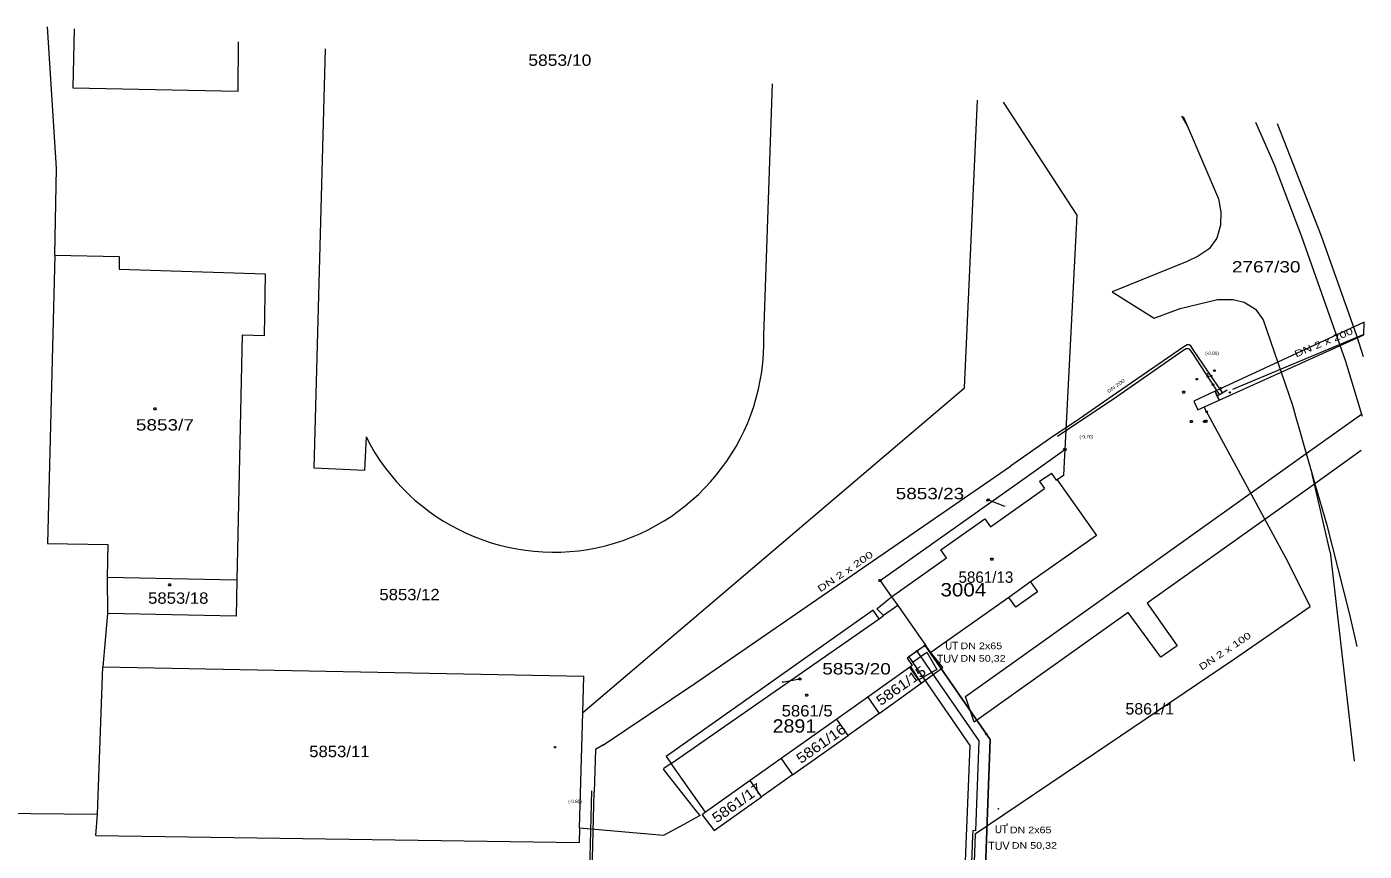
# Model space of a CAD drawing. Extents: x -725191 to -724881, y -978080 to -977718.
# Drawn here: x -725081.4 to -724880.9, y -977841.3 to -977717.7 of the extents above; entities that cross this region are included whole.
import ezdxf
from ezdxf.enums import TextEntityAlignment as Align

# ---------------------------------------------------------------- set-up
doc = ezdxf.new("R2010")
doc.units = 0
doc.header["$LTSCALE"] = 0.48
doc.header["$PDMODE"] = 32
doc.header["$PDSIZE"] = 0.24
for name, color, linetype, lineweight in [('1', 7, 'Continuous', 13), ('4', 7, 'Continuous', 13), ('46', 7, 'Continuous', 13), ('48', 7, 'Continuous', 13), ('5', 7, 'Continuous', 13), ('58', 7, 'Continuous', 13), ('63', 7, 'Continuous', 13), ('7', 7, 'Continuous', 13), ('8', 7, 'Continuous', 13)]:
    doc.layers.add(name, color=color, linetype=linetype, lineweight=lineweight)
doc.layers.add('2', color=7, linetype='Continuous')
doc.layers.add('20', color=7, linetype='Continuous')

msp = doc.modelspace()

# ---------------------------------------------------------------- linework, layer by layer
at = {"layer": '1'}
for p, q in [((-725077, -977738.94), (-725078.351, -977717.731)), ((-725074.329, -977718.048), (-725074.53, -977726.89)), ((-725038.37, -977783.91), (-725036.662, -977721.018)), ((-724970.94, -977764), (-724969.634, -977726.305)), ((-724940.83, -977771.89), (-724938.905, -977728.728)), ((-724935.028, -977729.034), (-724924, -977746)), ((-724907.45, -977732.56), (-724902.77, -977743.52)), ((-724887.3, -977749.13), (-724893.921, -977732.276)), ((-725077.23, -977751.96), (-725077, -977738.94)), ((-724924, -977746), (-724925.8, -977781.13)), ((-724882.02, -977764.07), (-724887.3, -977749.13)), ((-724881.025, -977767.222), (-724882.02, -977764.07)), ((-724998.05, -977820.52), (-724940.83, -977771.89)), ((-724889.6, -977781.71), (-724888.72, -977784.8)), ((-724927.04, -977785.71), (-724926.96, -977785.65)), ((-724936.94, -977792.71), (-724928.83, -977786.98)), ((-724886, -977796.5), (-724882.434, -977827.833)), ((-725070.03, -977813.69), (-724997.92, -977815.1)), ((-724998.05, -977820.52), (-724997.92, -977815.1)), ((-724955.36, -977818.24), (-724953.63, -977820.69)), ((-724998.55, -977837.86), (-724998.05, -977820.52)), ((-724966.61, -977829.88), (-724958.28, -977823.99)), ((-724985.58, -977827.13), (-724984.83, -977828.19)), ((-724978.36, -977838.24), (-724971.26, -977833.17)), ((-725071.09, -977838.97), (-725070.85, -977835.77)), ((-725071.09, -977838.97), (-724998.61, -977840.03))]:
    msp.add_line(p, q, dxfattribs=at)
for points in [[(-725074.53, -977726.89), (-725049.77, -977727.38), (-725049.675, -977719.992)], [(-724908.046, -977731.162), (-724907.45, -977732.56), (-724908.241, -977731.146)], [(-724902.77, -977743.52), (-724902.41, -977745.49), (-724902.45, -977747.49), (-724903.01, -977749.42), (-724904.15, -977751.03), (-724905.81, -977752.14), (-724907.48, -977752.94), (-724918.72, -977757.47), (-724912.38, -977761.4), (-724908.5, -977759.96), (-724902.92, -977758.61), (-724900.55, -977758.6), (-724898.9, -977759.02), (-724897.23, -977760.09), (-724896.04, -977761.68), (-724891.68, -977774.44)], [(-725077.23, -977751.96), (-725078.33, -977795.22), (-725069.29, -977795.35), (-725069.39, -977800.29)], [(-725077.23, -977751.96), (-725067.57, -977752.18), (-725067.61, -977754.09), (-725045.68, -977754.76), (-725045.86, -977764.05), (-725049.15, -977763.97), (-725049.94, -977800.71), (-725069.39, -977800.29)], [(-724891.68, -977774.44), (-724891.05, -977776.65), (-724890.76, -977777.65), (-724889.6, -977781.71)], [(-725030.58, -977779.22), (-725030.79, -977784.25), (-725038.37, -977783.91)], [(-724953.51, -977800.76), (-724931.26, -977785), (-724925.8, -977781.13)], [(-724925.8, -977781.13), (-724925.89, -977782.91), (-724925.95, -977784), (-724926, -977785)], [(-724926, -977785), (-724926.96, -977785.65), (-724921.07, -977793.98), (-724930.95, -977800.97), (-724929.91, -977802.44), (-724933.17, -977804.75), (-724934.21, -977803.28), (-724945.89, -977811.54), (-724946.67, -977810.44), (-724949.45, -977812.4), (-724948.67, -977813.51)], [(-724927.04, -977785.71), (-724927.75, -977784.71), (-724929.58, -977785.92), (-724928.83, -977786.98)], [(-724886, -977796.5), (-724888.37, -977786.29), (-724888.72, -977784.8), (-724888.31, -977786.24), (-724886.59, -977792.26)], [(-724943.52, -977797.36), (-724944.38, -977796.14), (-724937.8, -977791.49), (-724936.94, -977792.71)], [(-724886.59, -977792.26), (-724883.12, -977805.83), (-724882.035, -977810.662)], [(-724984.83, -977828.19), (-724953.63, -977806.49), (-724953, -977806), (-724954, -977805), (-724951.78, -977803.21), (-724943.52, -977797.36)], [(-725069.39, -977800.29), (-725069.35, -977805.69), (-725070.03, -977813.69)], [(-725049.94, -977800.71), (-725050.06, -977806.11), (-725069.35, -977805.69)], [(-724953.51, -977800.76), (-724952.97, -977801.52), (-724951.78, -977803.21)], [(-724951.78, -977803.21), (-724950.86, -977804.52), (-724946.67, -977810.44)], [(-724953.63, -977806.49), (-724954.56, -977805.18), (-724985.58, -977827.13)], [(-724953.63, -977820.69), (-724947.35, -977816.15), (-724944.08, -977813.8), (-724945.89, -977811.54)], [(-725085.88, -977835.64), (-725070.85, -977835.77), (-725070.03, -977813.69)], [(-724948.67, -977813.51), (-724948.87, -977813.65), (-724955.36, -977818.24)], [(-724953.63, -977820.69), (-724958.28, -977823.99), (-724960.01, -977821.54), (-724968.34, -977827.43), (-724966.61, -977829.88), (-724971.26, -977833.17), (-724973, -977830.72)], [(-724984.83, -977828.19), (-724985.93, -977828.95), (-724986, -977829)], [(-724973, -977830.72), (-724979.69, -977835.46), (-724984.83, -977828.19)], [(-724980.5, -977836), (-724981.03, -977835.33), (-724982.13, -977833.93), (-724985.83, -977829.22), (-724986, -977829)], [(-724980.5, -977836), (-724981.23, -977836.4), (-724982.37, -977837.02), (-724986, -977839)], [(-724979.69, -977835.46), (-724980.17, -977835.87), (-724978.36, -977838.24)], [(-724986, -977839), (-724998.55, -977837.86), (-724998.61, -977840.03)]]:
    msp.add_lwpolyline(points, dxfattribs=at)
msp.add_arc((-725002.4513, -977764.9825), 31.5266, 206.84653, 1.78587, dxfattribs=at)
at = {"layer": '4'}
for p, q in [((-724897.2, -977732.017), (-724894.4, -977738.4)), ((-724930.95, -977800.97), (-724934.21, -977803.28)), ((-724950.86, -977804.52), (-724953, -977806)), ((-724947.35, -977816.15), (-724948.87, -977813.65)), ((-724955.36, -977818.24), (-724960.01, -977821.54)), ((-724968.34, -977827.43), (-724973, -977830.72))]:
    msp.add_line(p, q, dxfattribs=at)
for points in [[(-724894.4, -977738.4), (-724890.3, -977749.17), (-724883.71, -977767.86)], [(-724883.71, -977767.86), (-724881.32, -977775.81), (-724881.232, -977776.106)], [(-724915.65, -977800.29), (-724889.6, -977781.71), (-724881.32, -977775.81), (-724881.223, -977775.74)], [(-724881.352, -977781.278), (-724888.31, -977786.24), (-724888.37, -977786.29), (-724913.46, -977804.17)], [(-724939.38, -977821.98), (-724940.71, -977818.13), (-724915.65, -977800.29)], [(-724913.46, -977804.17), (-724908.96, -977810.54), (-724911.4, -977812.26), (-724916.3, -977805.53), (-724939.38, -977821.98)]]:
    msp.add_lwpolyline(points, dxfattribs=at)
at = {"layer": '48'}
msp.add_lwpolyline([(-724904.36, -977769.719), (-724904.324, -977769.743), (-724904.328, -977769.786), (-724904.368, -977769.806), (-724904.405, -977769.782), (-724904.401, -977769.739)], close=True, dxfattribs=at)
for p in [(-724903.367, -977769.277), (-724906.017, -977770.566)]:
    msp.add_point(p, dxfattribs=at)
at = {"layer": '5'}
for points in [[(-725062.14, -977774.84), (-725062.05, -977774.99), (-725062.14, -977775.14), (-725062.32, -977775.14), (-725062.41, -977774.99), (-725062.32, -977774.84)], [(-724936.65, -977797.39), (-724936.56, -977797.54), (-724936.65, -977797.69), (-724936.83, -977797.69), (-724936.92, -977797.54), (-724936.83, -977797.39)], [(-725059.94, -977801.27), (-725059.85, -977801.42), (-725059.94, -977801.57), (-725060.12, -977801.57), (-725060.21, -977801.42), (-725060.12, -977801.27)], [(-724964.4, -977817.77), (-724964.31, -977817.92), (-724964.4, -977818.07), (-724964.58, -977818.07), (-724964.67, -977817.92), (-724964.58, -977817.77)]]:
    msp.add_lwpolyline(points, close=True, dxfattribs=at)
at = {"layer": '58'}
for points in [[(-724907.89, -977772.37), (-724907.8, -977772.52), (-724907.89, -977772.67), (-724908.07, -977772.67), (-724908.16, -977772.52), (-724908.07, -977772.37)], [(-724906.73, -977776.78), (-724906.64, -977776.93), (-724906.73, -977777.08), (-724906.91, -977777.08), (-724907, -977776.93), (-724906.91, -977776.78)], [(-724904.76, -977776.78), (-724904.67, -977776.93), (-724904.76, -977777.08), (-724904.94, -977777.08), (-724905.03, -977776.93), (-724904.94, -977776.78)], [(-724904.56, -977776.7), (-724904.47, -977776.85), (-724904.56, -977777), (-724904.74, -977777), (-724904.83, -977776.85), (-724904.74, -977776.7)]]:
    msp.add_lwpolyline(points, close=True, dxfattribs=at)
at = {"layer": '63'}
for p, q in [((-724880.905, -977762.044), (-724903.26, -977772.39)), ((-724902.66, -977773.73), (-724880.949, -977763.933)), ((-724880.947, -977763.868), (-724900.647, -977772.107)), ((-724901.44, -977772.23), (-724902.97, -977773.09)), ((-724927.61, -977779.16), (-724933.96, -977783.61)), ((-724939.222, -977838.756), (-724940.562, -977875.291))]:
    msp.add_line(p, q, dxfattribs=at)
for points in [[(-724880.905, -977762.032), (-724903.26, -977772.39), (-724902.66, -977773.73), (-724880.949, -977763.936)], [(-724880.905, -977762.032), (-724903.26, -977772.39), (-724902.66, -977773.73), (-724880.949, -977763.936)], [(-724904.47, -977770.179), (-724904.402, -977770.077), (-724904.28, -977770.089), (-724904.226, -977770.203), (-724904.294, -977770.305), (-724904.416, -977770.293)], [(-724903.735, -977770.091), (-724903.797, -977770.196), (-724903.919, -977770.192), (-724903.98, -977770.081), (-724903.919, -977769.976), (-724903.796, -977769.98)], [(-724903.718, -977771.376), (-724903.647, -977771.255), (-724903.507, -977771.26), (-724903.438, -977771.386), (-724903.508, -977771.507), (-724903.648, -977771.502)], [(-724902.3, -977771.94), (-724902.357, -977772.048), (-724902.479, -977772.05), (-724902.545, -977771.942), (-724902.489, -977771.833), (-724902.366, -977771.832)], [(-724902.97, -977773.09), (-724903.26, -977772.39), (-724906.45, -977773.87), (-724905.87, -977775.18), (-724902.66, -977773.73)], [(-724901.067, -977772.658), (-724901.139, -977772.609), (-724901.13, -977772.522), (-724901.049, -977772.484), (-724900.976, -977772.533), (-724900.985, -977772.62)], [(-724904.383, -977775.466), (-724904.455, -977775.586), (-724904.595, -977775.578), (-724904.663, -977775.451), (-724904.59, -977775.331), (-724904.45, -977775.339)], [(-724946.744, -977810.509), (-724949.211, -977812.215), (-724940.029, -977825.495), (-724942.001, -977873.733), (-724942.701, -977873.705), (-724942.819, -977876.703), (-724942.12, -977876.73), (-724943.226, -977905.12), (-724943.926, -977905.093), (-724944.039, -977908.091), (-724934.046, -977908.468), (-724936.266, -977967.326), (-724933.268, -977967.439), (-724931.048, -977908.581), (-724930.349, -977908.607), (-724930.236, -977905.61), (-724940.229, -977905.233), (-724938.908, -977876.858), (-724932.627, -977877.107), (-724932.509, -977874.109), (-724938.79, -977873.86), (-724936.993, -977824.611)], [(-724946.744, -977810.509), (-724949.211, -977812.215), (-724940.029, -977825.495), (-724942.001, -977873.733), (-724942.701, -977873.705), (-724942.819, -977876.703), (-724942.12, -977876.73), (-724943.226, -977905.12), (-724943.926, -977905.093), (-724944.039, -977908.091), (-724934.046, -977908.468), (-724936.266, -977967.326), (-724933.268, -977967.439), (-724931.048, -977908.581), (-724930.349, -977908.607), (-724930.236, -977905.61), (-724940.229, -977905.233), (-724938.908, -977876.858), (-724932.627, -977877.107), (-724932.509, -977874.109), (-724938.79, -977873.86), (-724936.993, -977824.611)], [(-724946.744, -977810.509), (-724949.211, -977812.215), (-724940.029, -977825.495), (-724942.001, -977873.733), (-724942.701, -977873.705), (-724942.819, -977876.703), (-724942.12, -977876.73), (-724943.226, -977905.12), (-724943.926, -977905.093), (-724944.039, -977908.091), (-724934.046, -977908.468), (-724936.266, -977967.326), (-724933.268, -977967.439), (-724931.048, -977908.581), (-724930.349, -977908.607), (-724930.236, -977905.61), (-724940.229, -977905.233), (-724938.908, -977876.858), (-724932.627, -977877.107), (-724932.509, -977874.109), (-724938.79, -977873.86), (-724936.993, -977824.611)], [(-724935.751, -977834.958), (-724935.72, -977834.972), (-724935.717, -977835.007), (-724935.747, -977835.028), (-724935.779, -977835.013), (-724935.781, -977834.979)], [(-724934.443, -977837.322), (-724934.475, -977837.306), (-724934.475, -977837.271), (-724934.445, -977837.252), (-724934.414, -977837.268), (-724934.413, -977837.303)]]:
    msp.add_lwpolyline(points, close=True, dxfattribs=at)
for points in [[(-724902.108, -977772.676), (-724906.6, -977766.06), (-724906.9, -977765.55), (-724907.14, -977765.44), (-724907.44, -977765.44), (-724907.95, -977765.74), (-724918.03, -977772.65), (-724924.24, -977776.96), (-724927.61, -977779.16)], [(-724902.598, -977772.886), (-724906.73, -977766.55), (-724907.05, -977766.1), (-724907.27, -977766.03), (-724907.6, -977766.02), (-724908.11, -977766.33), (-724918, -977773.2), (-724926.92, -977779.14)], [(-724939.222, -977838.756), (-724921.29, -977826.63), (-724900.35, -977812.47), (-724889.03, -977804.64), (-724892.31, -977797.99), (-724904.918, -977774.75)], [(-724995.11, -977825.47), (-724981.28, -977816.18), (-724933.96, -977783.61)], [(-724946.744, -977810.509), (-724949.211, -977812.215), (-724940.029, -977825.495), (-724942.001, -977873.733), (-724942.701, -977873.705), (-724942.819, -977876.703), (-724942.12, -977876.73), (-724943.226, -977905.12), (-724943.926, -977905.093), (-724944.039, -977908.091), (-724943.34, -977908.117), (-724934.046, -977908.468), (-724936.266, -977967.326), (-724933.268, -977967.439), (-724931.048, -977908.581), (-724930.349, -977908.607), (-724930.236, -977905.61), (-724930.935, -977905.583), (-724933.933, -977905.47)], [(-724948.678, -977813.053), (-724946.5, -977811.51), (-724944.98, -977814.1), (-724947.67, -977815.66), (-724949.073, -977813.691)], [(-724947.978, -977811.362), (-724938.71, -977824.766), (-724939.204, -977838.257), (-724939.604, -977838.242), (-724939.636, -977839.037)], [(-724946.744, -977810.509), (-724936.993, -977824.611), (-724938.79, -977873.86)], [(-724995.056, -977825.449), (-724996.156, -977826.109), (-724996.376, -977832.498)], [(-724996.78, -977832.3), (-724997.07, -977844.29), (-724997.12, -977846.74), (-724997.13, -977847.34), (-724997.28, -977847.6), (-724997.53, -977847.71), (-724998.14, -977847.69), (-725010.12, -977847.35), (-725022.19, -977846.94), (-725034.17, -977846.58), (-725046.16, -977846.17), (-725052.297, -977846.041), (-725054.5, -977845.99), (-725056.407, -977845.955), (-725066.64, -977845.74), (-725078.71, -977845.31), (-725090.71, -977845.05), (-725102.48, -977844.75), (-725114.72, -977844.37)], [(-725114.7, -977844.66), (-725102.42, -977845.11), (-725090.73, -977845.48), (-725078.78, -977845.7), (-725066.72, -977846.15), (-725056.681, -977846.35), (-725054.7, -977846.39), (-725052.296, -977846.437), (-725045.64, -977846.57), (-725033.74, -977847.05), (-725021.75, -977847.47), (-725009.76, -977847.84), (-724997.78, -977848.14), (-724997.15, -977848.14), (-724996.88, -977847.98), (-724996.72, -977847.77), (-724996.68, -977847.12), (-724996.65, -977844.4), (-724996.35, -977832.44)], [(-724939.636, -977839.037), (-724940.981, -977875.775), (-724940.582, -977875.791), (-724940.821, -977881.133), (-724941.626, -977902.478), (-724941.784, -977906.675), (-724932.491, -977907.026), (-724934.684, -977965.184)]]:
    msp.add_lwpolyline(points, dxfattribs=at)
for p in [(-724947.978, -977811.362), (-724946.744, -977810.509), (-724937.562, -977823.788), (-725002.25, -977825.739)]:
    msp.add_point(p, dxfattribs=at)
at = {"layer": '7'}
for p, q in [((-724934.78, -977789.64), (-724937.32, -977788.67)), ((-724968.18, -977815.97), (-724965.53, -977815.5))]:
    msp.add_line(p, q, dxfattribs=at)
for points in [[(-724937.428, -977788.532), (-724937.255, -977788.502), (-724937.148, -977788.64), (-724937.212, -977788.808), (-724937.385, -977788.838), (-724937.492, -977788.7)], [(-724965.367, -977815.562), (-724965.499, -977815.677), (-724965.662, -977815.615), (-724965.693, -977815.438), (-724965.561, -977815.323), (-724965.398, -977815.385)]]:
    msp.add_lwpolyline(points, close=True, dxfattribs=at)
at = {"layer": '8'}
for points in [[(-724925.71, -977780.98), (-724925.62, -977781.13), (-724925.71, -977781.28), (-724925.89, -977781.28), (-724925.98, -977781.13), (-724925.89, -977780.98)], [(-724953.42, -977800.61), (-724953.33, -977800.76), (-724953.42, -977800.91), (-724953.6, -977800.91), (-724953.69, -977800.76), (-724953.6, -977800.61)]]:
    msp.add_lwpolyline(points, close=True, dxfattribs=at)

# ---------------------------------------------------------------- texts
at = {"layer": '2'}
for s, height, width, p in [('5853/10', 1.7, 1.15, (-725006.243, -977723.59)), ('2767/30', 1.7, 1.25, (-724900.743, -977754.57)), ('5853/7', 1.7, 1.25, (-725065.083, -977778.27)), ('5853/23', 0.1, 1.25, (-724934.766, -977789.64)), ('5853/12', 1.7, 1.1, (-725028.573, -977803.71)), ('5853/18', 1.7, 1.1, (-725063.253, -977804.24)), ('5861/5', 1.7, 1.1, (-724968.263, -977821.14)), ('5861/1', 1.7, 1.05, (-724916.713, -977820.84)), ('5853/11', 1.7, 1.1, (-725039.093, -977827.23))]:
    msp.add_text(s, height=height, dxfattribs=dict(at, width=width)).set_placement(p)
msp.add_text('5861/13', height=1.7, dxfattribs=at).set_placement((-724941.743, -977801.1))
at = {"layer": '2', "width": 1.15}
for s, p in [('5861/15', (-724953.405, -977819.597)), ('5861/16', (-724965.375, -977828.277)), ('5861/17', (-724978.015, -977837.177))]:
    msp.add_text(s, height=1.53, rotation=35.122, dxfattribs=at).set_placement(p)
at = {"layer": '2', "width": 1.25}
msp.add_text('5853/20', height=0.1, dxfattribs=at).set_placement((-724968.18, -977815.97), align=Align.CENTER)
at = {"layer": '20', "width": 1.1}
msp.add_text('2891', height=2, dxfattribs=at).set_placement((-724966.343, -977823.562), align=Align.CENTER)
at = {"layer": '46'}
for s, p in [('(-0,80)', (-724903.7215, -977766.934)), ('(-0,70)', (-724922.5905, -977779.425)), ('(-0.80)', (-724999.238, -977834.121))]:
    msp.add_text(s, height=0.5, dxfattribs=at).set_placement(p, align=Align.CENTER)
at = {"layer": '63'}
for s, height, rotation, width, p in [('DN 2 x 200', 1, 22.46, 1.4, (-724886.7965, -977765.5269)), ('DN 200', 0.5, 35.924, 1.35, (-724917.9872, -977771.7754)), ('DN 2 x 200', 1, 34.206, 1.45, (-724958.4486, -977799.8224)), ('DN 2 x 100', 1, 33.805, 1.35, (-724901.5132, -977811.7567))]:
    msp.add_text(s, height=height, rotation=rotation, dxfattribs=dict(at, width=width)).set_placement(p, align=Align.CENTER)
at = {"layer": '63', "width": 1.2}
for s, p in [('DN 2x65', (-724938.3215, -977811.049)), ('DN 50,32', (-724938.071, -977812.929)), ('DN 2x65', (-724930.9275, -977838.647)), ('DN 50,32', (-724930.363, -977840.978))]:
    msp.add_text(s, height=1, dxfattribs=at).set_placement(p, align=Align.CENTER)
at = {"layer": '7', "width": 1.25}
msp.add_text('5853/23', height=1.7, dxfattribs=at).set_placement((-724940.888, -977788.57), align=Align.RIGHT)
at = {"layer": '7'}
for s, height, width, p in [('3004', 2, 1.15, (-724941.0185, -977803.138)), ('UT', 1.2, 0.9, (-724942.7715, -977811.124)), ('5853/20', 1.7, 1.25, (-724957.03, -977814.84)), ('UT', 1.2, 0.9, (-724935.3135, -977838.647))]:
    msp.add_text(s, height=height, dxfattribs=dict(at, width=width)).set_placement(p, align=Align.CENTER)
for p in [(-724943.398, -977813.079), (-724935.69, -977841.129)]:
    msp.add_text('TUV', height=1.2, dxfattribs=at).set_placement(p, align=Align.CENTER)

doc.saveas('drawing.dxf')
